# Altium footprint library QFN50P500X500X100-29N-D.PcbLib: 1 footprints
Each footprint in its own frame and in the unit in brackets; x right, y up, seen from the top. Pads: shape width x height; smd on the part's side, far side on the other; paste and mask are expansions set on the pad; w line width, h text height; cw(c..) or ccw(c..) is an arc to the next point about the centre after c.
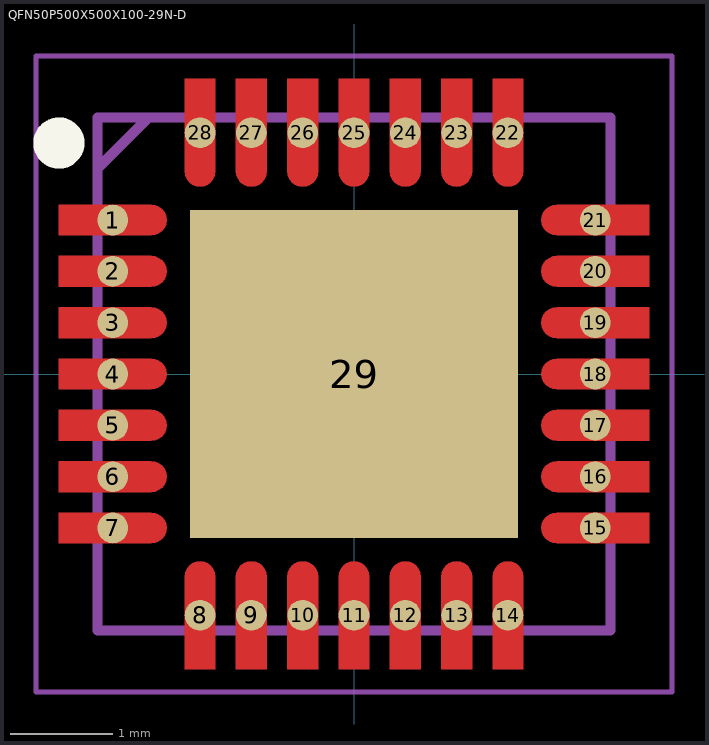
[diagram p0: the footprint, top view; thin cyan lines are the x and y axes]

## QFN50P500X500X100-29N-D [mm]
pads (29):
  round 0.3 smd: 1(-2.35,1.5) 2(-2.35,1) 3(-2.35,0.5) 4(-2.35,0) 5(-2.35,-0.5) 6(-2.35,-1) 7(-2.35,-1.5) 8(-1.5,-2.35) 9(-1,-2.35) 10(-0.5,-2.35) 11(0,-2.35) 12(0.5,-2.35) 13(1,-2.35) 14(1.5,-2.35) 15(2.35,-1.5) 16(2.35,-1) 17(2.35,-0.5) 18(2.35,0) 19(2.35,0.5) 20(2.35,1) 21(2.35,1.5) 22(1.5,2.35) 23(1,2.35) 24(0.5,2.35) 25(0,2.35) 26(-0.5,2.35) 27(-1,2.35) 28(-1.5,2.35)
  rect 3.2x3.2 smd: 29(0,0)
L1-Top Layer:
  region: -2.875,1.65 -1.975,1.65 -1.936,1.645 -1.9,1.63 -1.869,1.606 -1.845,1.575 -1.83,1.539 -1.825,1.5 -1.83,1.461 -1.845,1.425 -1.869,1.394 -1.9,1.37 -1.936,1.355 -1.975,1.35 -2.875,1.35
  region: -2.875,1.15 -1.975,1.15 -1.936,1.145 -1.9,1.13 -1.869,1.106 -1.845,1.075 -1.83,1.039 -1.825,1 -1.83,0.961 -1.845,0.925 -1.869,0.894 -1.9,0.87 -1.936,0.855 -1.975,0.85 -2.875,0.85
  region: -2.875,0.65 -1.975,0.65 -1.936,0.645 -1.9,0.63 -1.869,0.606 -1.845,0.575 -1.83,0.539 -1.825,0.5 -1.83,0.461 -1.845,0.425 -1.869,0.394 -1.9,0.37 -1.936,0.355 -1.975,0.35 -2.875,0.35
  region: -2.875,0.15 -1.975,0.15 -1.936,0.145 -1.9,0.13 -1.869,0.106 -1.845,0.075 -1.83,0.039 -1.825,0 -1.83,-0.039 -1.845,-0.075 -1.869,-0.106 -1.9,-0.13 -1.936,-0.145 -1.975,-0.15 -2.875,-0.15
  region: -2.875,-0.35 -1.975,-0.35 -1.936,-0.355 -1.9,-0.37 -1.869,-0.394 -1.845,-0.425 -1.83,-0.461 -1.825,-0.5 -1.83,-0.539 -1.845,-0.575 -1.869,-0.606 -1.9,-0.63 -1.936,-0.645 -1.975,-0.65 -2.875,-0.65
  region: -2.875,-0.85 -1.975,-0.85 -1.936,-0.855 -1.9,-0.87 -1.869,-0.894 -1.845,-0.925 -1.83,-0.961 -1.825,-1 -1.83,-1.039 -1.845,-1.075 -1.869,-1.106 -1.9,-1.13 -1.936,-1.145 -1.975,-1.15 -2.875,-1.15
  region: -2.875,-1.35 -1.975,-1.35 -1.936,-1.355 -1.9,-1.37 -1.869,-1.394 -1.845,-1.425 -1.83,-1.461 -1.825,-1.5 -1.83,-1.539 -1.845,-1.575 -1.869,-1.606 -1.9,-1.63 -1.936,-1.645 -1.975,-1.65 -2.875,-1.65
  region: -1.65,-2.875 -1.65,-1.975 -1.645,-1.936 -1.63,-1.9 -1.606,-1.869 -1.575,-1.845 -1.539,-1.83 -1.5,-1.825 -1.461,-1.83 -1.425,-1.845 -1.394,-1.869 -1.37,-1.9 -1.355,-1.936 -1.35,-1.975 -1.35,-2.875
  region: -1.15,-2.875 -1.15,-1.975 -1.145,-1.936 -1.13,-1.9 -1.106,-1.869 -1.075,-1.845 -1.039,-1.83 -1,-1.825 -0.961,-1.83 -0.925,-1.845 -0.894,-1.869 -0.87,-1.9 -0.855,-1.936 -0.85,-1.975 -0.85,-2.875
  region: -0.65,-2.875 -0.65,-1.975 -0.645,-1.936 -0.63,-1.9 -0.606,-1.869 -0.575,-1.845 -0.539,-1.83 -0.5,-1.825 -0.461,-1.83 -0.425,-1.845 -0.394,-1.869 -0.37,-1.9 -0.355,-1.936 -0.35,-1.975 -0.35,-2.875
  region: -0.15,-2.875 -0.15,-1.975 -0.145,-1.936 -0.13,-1.9 -0.106,-1.869 -0.075,-1.845 -0.039,-1.83 0,-1.825 0.039,-1.83 0.075,-1.845 0.106,-1.869 0.13,-1.9 0.145,-1.936 0.15,-1.975 0.15,-2.875
  region: 0.35,-2.875 0.35,-1.975 0.355,-1.936 0.37,-1.9 0.394,-1.869 0.425,-1.845 0.461,-1.83 0.5,-1.825 0.539,-1.83 0.575,-1.845 0.606,-1.869 0.63,-1.9 0.645,-1.936 0.65,-1.975 0.65,-2.875
  region: 0.85,-2.875 0.85,-1.975 0.855,-1.936 0.87,-1.9 0.894,-1.869 0.925,-1.845 0.961,-1.83 1,-1.825 1.039,-1.83 1.075,-1.845 1.106,-1.869 1.13,-1.9 1.145,-1.936 1.15,-1.975 1.15,-2.875
  region: 1.35,-2.875 1.35,-1.975 1.355,-1.936 1.37,-1.9 1.394,-1.869 1.425,-1.845 1.461,-1.83 1.5,-1.825 1.539,-1.83 1.575,-1.845 1.606,-1.869 1.63,-1.9 1.645,-1.936 1.65,-1.975 1.65,-2.875
  region: 2.875,-1.65 1.975,-1.65 1.936,-1.645 1.9,-1.63 1.869,-1.606 1.845,-1.575 1.83,-1.539 1.825,-1.5 1.83,-1.461 1.845,-1.425 1.869,-1.394 1.9,-1.37 1.936,-1.355 1.975,-1.35 2.875,-1.35
  region: 2.875,-1.15 1.975,-1.15 1.936,-1.145 1.9,-1.13 1.869,-1.106 1.845,-1.075 1.83,-1.039 1.825,-1 1.83,-0.961 1.845,-0.925 1.869,-0.894 1.9,-0.87 1.936,-0.855 1.975,-0.85 2.875,-0.85
  region: 2.875,-0.65 1.975,-0.65 1.936,-0.645 1.9,-0.63 1.869,-0.606 1.845,-0.575 1.83,-0.539 1.825,-0.5 1.83,-0.461 1.845,-0.425 1.869,-0.394 1.9,-0.37 1.936,-0.355 1.975,-0.35 2.875,-0.35
  region: 2.875,-0.15 1.975,-0.15 1.936,-0.145 1.9,-0.13 1.869,-0.106 1.845,-0.075 1.83,-0.039 1.825,0 1.83,0.039 1.845,0.075 1.869,0.106 1.9,0.13 1.936,0.145 1.975,0.15 2.875,0.15
  region: 2.875,0.35 1.975,0.35 1.936,0.355 1.9,0.37 1.869,0.394 1.845,0.425 1.83,0.461 1.825,0.5 1.83,0.539 1.845,0.575 1.869,0.606 1.9,0.63 1.936,0.645 1.975,0.65 2.875,0.65
  region: 2.875,0.85 1.975,0.85 1.936,0.855 1.9,0.87 1.869,0.894 1.845,0.925 1.83,0.961 1.825,1 1.83,1.039 1.845,1.075 1.869,1.106 1.9,1.13 1.936,1.145 1.975,1.15 2.875,1.15
  region: 2.875,1.35 1.975,1.35 1.936,1.355 1.9,1.37 1.869,1.394 1.845,1.425 1.83,1.461 1.825,1.5 1.83,1.539 1.845,1.575 1.869,1.606 1.9,1.63 1.936,1.645 1.975,1.65 2.875,1.65
  region: 1.65,2.875 1.65,1.975 1.645,1.936 1.63,1.9 1.606,1.869 1.575,1.845 1.539,1.83 1.5,1.825 1.461,1.83 1.425,1.845 1.394,1.869 1.37,1.9 1.355,1.936 1.35,1.975 1.35,2.875
  region: 1.15,2.875 1.15,1.975 1.145,1.936 1.13,1.9 1.106,1.869 1.075,1.845 1.039,1.83 1,1.825 0.961,1.83 0.925,1.845 0.894,1.869 0.87,1.9 0.855,1.936 0.85,1.975 0.85,2.875
  region: 0.65,2.875 0.65,1.975 0.645,1.936 0.63,1.9 0.606,1.869 0.575,1.845 0.539,1.83 0.5,1.825 0.461,1.83 0.425,1.845 0.394,1.869 0.37,1.9 0.355,1.936 0.35,1.975 0.35,2.875
  region: 0.15,2.875 0.15,1.975 0.145,1.936 0.13,1.9 0.106,1.869 0.075,1.845 0.039,1.83 0,1.825 -0.039,1.83 -0.075,1.845 -0.106,1.869 -0.13,1.9 -0.145,1.936 -0.15,1.975 -0.15,2.875
  region: -0.35,2.875 -0.35,1.975 -0.355,1.936 -0.37,1.9 -0.394,1.869 -0.425,1.845 -0.461,1.83 -0.5,1.825 -0.539,1.83 -0.575,1.845 -0.606,1.869 -0.63,1.9 -0.645,1.936 -0.65,1.975 -0.65,2.875
  region: -0.85,2.875 -0.85,1.975 -0.855,1.936 -0.87,1.9 -0.894,1.869 -0.925,1.845 -0.961,1.83 -1,1.825 -1.039,1.83 -1.075,1.845 -1.106,1.869 -1.13,1.9 -1.145,1.936 -1.15,1.975 -1.15,2.875
  region: -1.35,2.875 -1.35,1.975 -1.355,1.936 -1.37,1.9 -1.394,1.869 -1.425,1.845 -1.461,1.83 -1.5,1.825 -1.539,1.83 -1.575,1.845 -1.606,1.869 -1.63,1.9 -1.645,1.936 -1.65,1.975 -1.65,2.875
Top Overlay:
  circle w0.25: c-2.875,2.25 r0.125
Mechanical 15:
  lines w0.1: -2.5,2 -2,2.5 ; -2.5,-2.5 2.5,-2.5 2.5,2.5 -2.5,2.5 -2.5,-2.5
Mechanical 20:
  lines w0.05: -3.1,-3.1 3.1,-3.1 3.1,3.1 -3.1,3.1 -3.1,-3.1
3D body "ECE1088-DZK.stp": height 5.8, standoff -4.65, extent -10,-3.376 10,3.376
